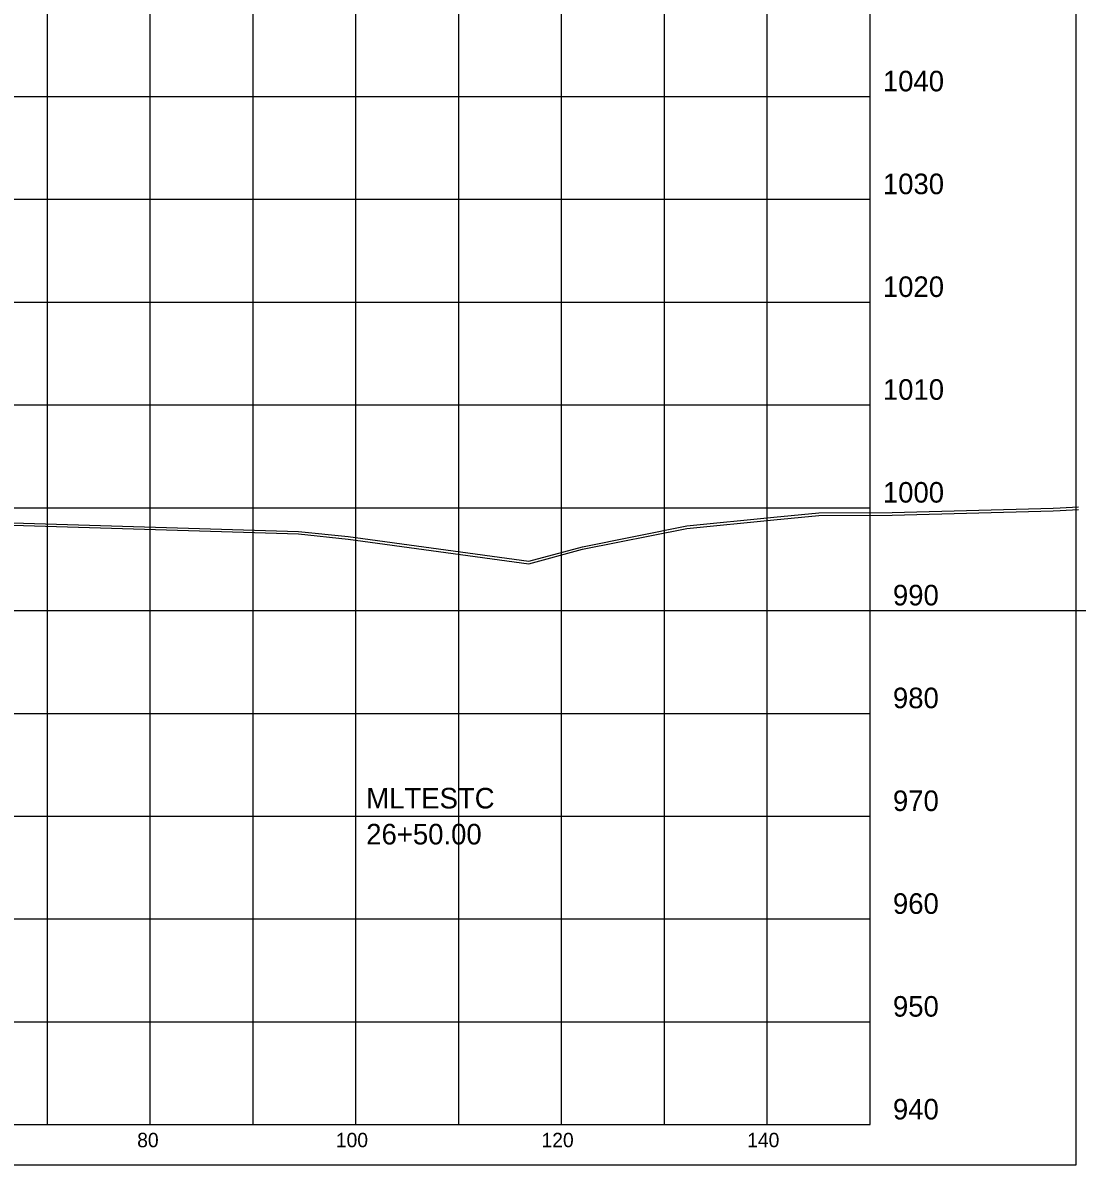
# Model space of a CAD drawing. Extents: x 1131015 to 1136271, y 133453 to 174329.
# Drawn here: x 1132408.1 to 1132510.6, y 158613.7 to 158724.8 of the extents above; entities that cross this region are included whole.
import ezdxf

# ---------------------------------------------------------------- set-up
doc = ezdxf.new("R2010")
doc.units = 0
for name, color, linetype in [('DESIGN - SHEET - Corner Text', 7, 'Continuous'), ('DESIGN - SHEET - Light Grid', 7, 'Continuous'), ('DESIGN - SHEET - Linework', 7, 'Continuous'), ('DESIGN - SHEET - Plot Shape', 7, 'Continuous'), ('DESIGN - TYPICAL - Warning Text', 7, 'Continuous'), ('SURVEY - GROUND - Bottom of Topsoil Layer', 7, 'Continuous'), ('SURVEY - GROUND - Top of Ground', 7, 'Continuous')]:
    doc.layers.add(name, color=color, linetype=linetype)

msp = doc.modelspace()

# ---------------------------------------------------------------- linework, layer by layer
at = {"layer": 'DESIGN - SHEET - Light Grid'}
msp.add_line((1132340.46, 158667.66), (1132640.46, 158667.66), dxfattribs=at)
at = {"layer": 'DESIGN - SHEET - Linework'}
for p, q in [((1132410.46, 158617.66), (1132410.46, 158827.66)), ((1132420.46, 158617.66), (1132420.46, 158827.66)), ((1132430.46, 158617.66), (1132430.46, 158827.66)), ((1132440.46, 158617.66), (1132440.46, 158827.66)), ((1132450.46, 158617.66), (1132450.46, 158827.66)), ((1132460.46, 158617.66), (1132460.46, 158827.66)), ((1132470.46, 158617.66), (1132470.46, 158827.66)), ((1132480.46, 158617.66), (1132480.46, 158827.66)), ((1132190.46, 158717.66), (1132490.46, 158717.66)), ((1132190.46, 158707.66), (1132490.46, 158707.66)), ((1132190.46, 158697.66), (1132490.46, 158697.66)), ((1132190.46, 158687.66), (1132490.46, 158687.66)), ((1132190.46, 158677.66), (1132490.46, 158677.66)), ((1132190.46, 158667.66), (1132490.46, 158667.66)), ((1132190.46, 158657.66), (1132490.46, 158657.66)), ((1132190.46, 158647.66), (1132490.46, 158647.66)), ((1132190.46, 158637.66), (1132490.46, 158637.66)), ((1132190.46, 158627.66), (1132490.46, 158627.66))]:
    msp.add_line(p, q, dxfattribs=at)
msp.add_lwpolyline([(1132190.46, 158827.66), (1132190.46, 158617.66), (1132490.46, 158617.66), (1132490.46, 158827.66)], dxfattribs=at)
at = {"layer": 'DESIGN - SHEET - Plot Shape'}
msp.add_lwpolyline([(1132170.46, 158831.6), (1132510.46, 158831.6), (1132510.46, 158613.72), (1132170.46, 158613.72)], close=True, dxfattribs=at)
at = {"layer": 'SURVEY - GROUND - Bottom of Topsoil Layer'}
for p, q in [((1132492.61, 158676.95), (1132508.27, 158677.36)), ((1132508.27, 158677.36), (1132508.93, 158677.39)), ((1132508.93, 158677.39), (1132510.73, 158677.49)), ((1132472.63, 158675.64), (1132481.11, 158676.5)), ((1132481.11, 158676.5), (1132485.47, 158676.9)), ((1132485.47, 158676.9), (1132492.61, 158676.95)), ((1132405.98, 158675.99), (1132434.89, 158675.11)), ((1132462.48, 158673.62), (1132472.63, 158675.64)), ((1132434.89, 158675.11), (1132439.71, 158674.6)), ((1132439.71, 158674.6), (1132457.27, 158672.22)), ((1132457.27, 158672.22), (1132462.48, 158673.62))]:
    msp.add_line(p, q, dxfattribs=at)
at = {"layer": 'SURVEY - GROUND - Top of Ground'}
for p, q in [((1132492.61, 158677.2), (1132508.27, 158677.61)), ((1132508.27, 158677.61), (1132508.93, 158677.64)), ((1132508.93, 158677.64), (1132510.73, 158677.74)), ((1132472.63, 158675.89), (1132481.11, 158676.75)), ((1132481.11, 158676.75), (1132485.47, 158677.15)), ((1132485.47, 158677.15), (1132492.61, 158677.2)), ((1132405.98, 158676.24), (1132434.89, 158675.36)), ((1132434.89, 158675.36), (1132439.71, 158674.85)), ((1132462.48, 158673.87), (1132472.63, 158675.89)), ((1132439.71, 158674.85), (1132457.27, 158672.47)), ((1132457.27, 158672.47), (1132462.48, 158673.87))]:
    msp.add_line(p, q, dxfattribs=at)

# ---------------------------------------------------------------- texts
at = {"layer": 'DESIGN - SHEET - Corner Text'}
for s, height, p in [('1040', 2, (1132491.7, 158718.16)), ('1030', 2, (1132491.7, 158708.16)), ('1020', 2, (1132491.7, 158698.16)), ('1010', 2, (1132491.7, 158688.16)), ('1000', 2, (1132491.7, 158678.16)), ('990', 2, (1132492.68, 158668.16)), ('980', 2, (1132492.68, 158658.16)), ('970', 2, (1132492.68, 158648.16)), ('960', 2, (1132492.68, 158638.16)), ('950', 2, (1132492.68, 158628.16)), ('940', 2, (1132492.68, 158618.16)), ('80', 1.4, (1132419.19, 158615.46)), ('100', 1.4, (1132438.51, 158615.46)), ('120', 1.4, (1132458.51, 158615.46)), ('140', 1.4, (1132478.51, 158615.46))]:
    msp.add_text(s, height=height, dxfattribs=at).set_placement(p)
at = {"layer": 'DESIGN - TYPICAL - Warning Text'}
for s, p in [('MLTESTC', (1132441.46, 158648.41)), ('26+50.00', (1132441.46, 158644.91))]:
    msp.add_text(s, height=2, dxfattribs=at).set_placement(p)

doc.saveas('drawing.dxf')
